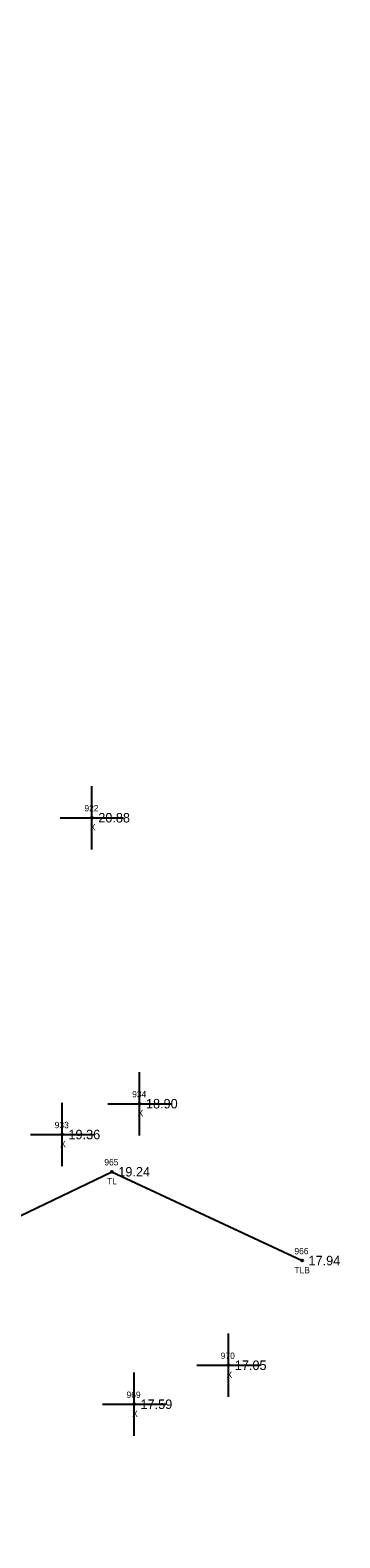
# Model space of a CAD drawing. Extents: x 2042211 to 2045853, y 303080 to 309569.
# Drawn here: x 2042989.1 to 2043038.1, y 306802.7 to 307040.8 of the extents above; entities that cross this region are included whole.
import ezdxf

# ---------------------------------------------------------------- set-up
doc = ezdxf.new("R2010")
doc.units = 0
for name, color, linetype in [('BR_500YR_SCOUR', 7, 'Continuous'), ('RD_EX_Misc', 7, 'Continuous'), ('RD_EX_Misc_txCode', 7, 'Continuous'), ('RD_EX_TX_Misc_ELEV', 7, 'Continuous'), ('RD_EX_TX_VEG_ELEV', 7, 'Continuous'), ('RD_EX_VEG_txCode', 7, 'Continuous'), ('RD_SMD_Locator', 7, 'Continuous')]:
    doc.layers.add(name, color=color, linetype=linetype)

msp = doc.modelspace()

# ---------------------------------------------------------------- linework, layer by layer
at = {"layer": 'BR_500YR_SCOUR'}
msp.add_lwpolyline([(2042880.44, 307351.7), (2042880.19, 307284.9), (2042884.99, 307224.08), (2042886.48, 307195.22), (2042890.83, 307127.55), (2042909.45, 307007.86), (2042916.1, 306960.95), (2042918.56, 306940.03), (2042926.66, 306909), (2042942.91, 306849.91), (2042954.33, 306802.72), (2042963.56, 306806.84), (2042974.33, 306847.25), (2043002.07, 306860.54), (2043032.14, 306846.51)], dxfattribs=at)
for centre in [(2043002.07, 306860.54), (2043032.14, 306846.51)]:
    msp.add_circle(centre, 0.15, dxfattribs=at)
at = {"layer": 'RD_EX_Misc'}
for p, q in [((2042998.9, 306911.45), (2042998.9, 306921.45)), ((2042993.9, 306916.45), (2043003.9, 306916.45)), ((2043006.44, 306866.29), (2043006.44, 306876.29)), ((2042994.19, 306861.42), (2042994.19, 306871.42)), ((2043001.44, 306871.29), (2043011.44, 306871.29)), ((2042989.19, 306866.42), (2042999.19, 306866.42)), ((2043020.49, 306824.98), (2043020.49, 306834.98)), ((2043015.49, 306829.98), (2043025.49, 306829.98)), ((2043005.58, 306818.82), (2043005.58, 306828.82)), ((2043000.58, 306823.82), (2043010.58, 306823.82))]:
    msp.add_line(p, q, dxfattribs=at)
at = {"layer": 'RD_SMD_Locator'}
for centre in [(2042998.9, 306916.45), (2043006.44, 306871.29), (2042994.19, 306866.42), (2043020.49, 306829.98), (2043005.58, 306823.82)]:
    msp.add_circle(centre, 0.15, dxfattribs=at)

# ---------------------------------------------------------------- texts
at = {"layer": 'RD_EX_Misc_txCode'}
for s, p in [('922', (2042997.71, 306917.45)), ('X', (2042998.58, 306914.45)), ('934', (2043005.26, 306872.29)), ('X', (2043006.12, 306869.29)), ('933', (2042993.01, 306867.42)), ('X', (2042993.88, 306864.42)), ('970', (2043019.27, 306830.98)), ('X', (2043020.18, 306827.98)), ('969', (2043004.37, 306824.82)), ('X', (2043005.26, 306821.82))]:
    msp.add_text(s, height=1, dxfattribs=at).set_placement(p)
at = {"layer": 'RD_EX_TX_Misc_ELEV'}
for s, p in [('20.88', (2042999.9, 306915.7)), ('18.90', (2043007.44, 306870.54)), ('19.36', (2042995.19, 306865.67)), ('17.05', (2043021.49, 306829.23)), ('17.59', (2043006.58, 306823.07))]:
    msp.add_text(s, height=1.5, dxfattribs=at).set_placement(p)
at = {"layer": 'RD_EX_TX_VEG_ELEV'}
for s, p in [('19.24', (2043003.07, 306859.79)), ('17.94', (2043033.14, 306845.76))]:
    msp.add_text(s, height=1.5, dxfattribs=at).set_placement(p)
at = {"layer": 'RD_EX_VEG_txCode'}
for s, p in [('965', (2043000.86, 306861.54)), ('TL', (2043001.3, 306858.54)), ('966', (2043030.91, 306847.51)), ('TLB', (2043030.9, 306844.51))]:
    msp.add_text(s, height=1, dxfattribs=at).set_placement(p)

doc.saveas('drawing.dxf')
